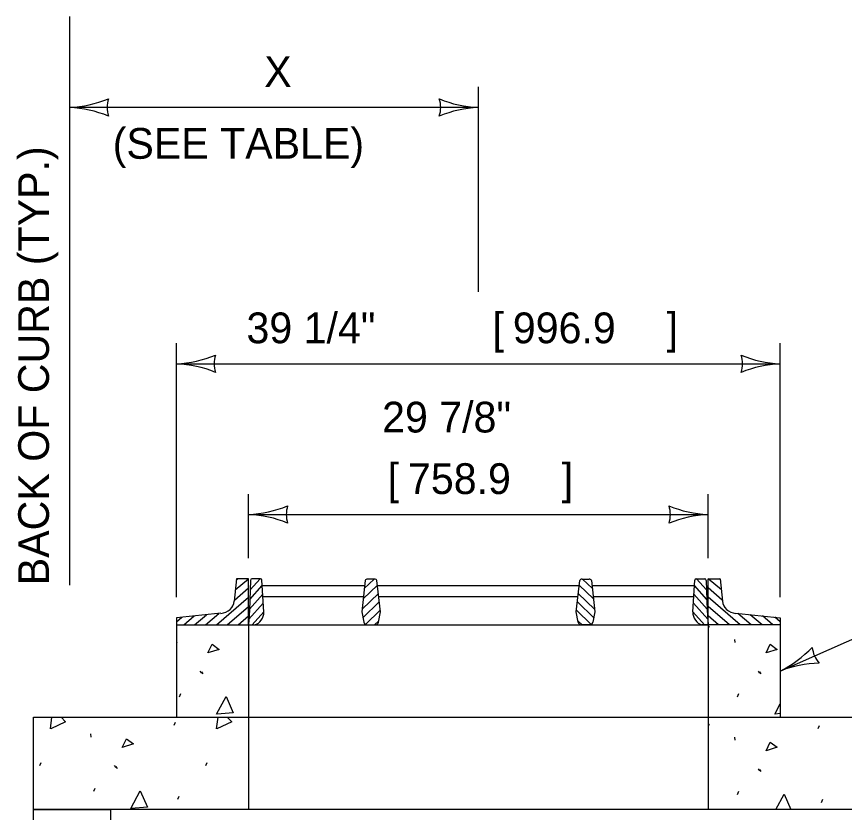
# Model space of a CAD drawing. Extents: x 49991.4 to 50041.6, y 49987.6 to 50011.4.
# Drawn here: x 50025.96 to 50027.575, y 49992.221 to 49993.773 of the extents above; entities that cross this region are included whole.
import ezdxf

# ---------------------------------------------------------------- set-up
doc = ezdxf.new("R2010")
doc.units = 0
for name, color, linetype in [('Level 1', 7, 'Continuous'), ('Level 2', 7, 'Continuous'), ('Level 3', 7, 'Continuous')]:
    doc.layers.add(name, color=color, linetype=linetype)

msp = doc.modelspace()

# ---------------------------------------------------------------- linework, layer by layer
at = {"layer": 'Level 1'}
for p, q in [((50026.3889, 49992.6769), (50026.3848, 49992.633)), ((50026.3868, 49992.655), (50026.4124, 49992.6769)), ((50026.3887, 49992.6748), (50026.3912, 49992.6769)), ((50026.4128, 49992.6769), (50026.3889, 49992.6769)), ((50026.4128, 49992.5869), (50026.4128, 49992.6769)), ((50026.4156, 49992.6553), (50026.435, 49992.6769)), ((50026.4358, 49992.6769), (50026.4192, 49992.6769)), ((50026.6385, 49992.6577), (50026.6574, 49992.676)), ((50026.6585, 49992.676), (50026.6449, 49992.676)), ((50027.0634, 49992.676), (50027.077, 49992.676)), ((50027.0834, 49992.6577), (50027.0645, 49992.676)), ((50027.2861, 49992.6769), (50027.3027, 49992.6769)), ((50027.3063, 49992.6553), (50027.2869, 49992.6769)), ((50027.3091, 49992.5869), (50027.3091, 49992.6769)), ((50027.3091, 49992.6769), (50027.3331, 49992.6769)), ((50027.3351, 49992.655), (50027.3095, 49992.6769)), ((50027.3333, 49992.6748), (50027.3307, 49992.6769)), ((50027.3331, 49992.6769), (50027.3371, 49992.633)), ((50026.385, 49992.6353), (50026.4128, 49992.6591)), ((50026.4162, 49992.6738), (50026.4142, 49992.6158)), ((50026.4149, 49992.6364), (50026.4394, 49992.6636)), ((50026.4424, 49992.6127), (50026.4388, 49992.6739)), ((50026.4394, 49992.6636), (50026.6391, 49992.6636)), ((50026.6401, 49992.6732), (50026.6336, 49992.6124)), ((50026.6363, 49992.6376), (50026.6642, 49992.6645)), ((50026.6698, 49992.6124), (50026.6632, 49992.6732)), ((50026.6643, 49992.6636), (50027.0576, 49992.6636)), ((50027.0521, 49992.6124), (50027.0587, 49992.6732)), ((50027.0856, 49992.6376), (50027.0577, 49992.6645)), ((50027.0818, 49992.6732), (50027.0883, 49992.6124)), ((50027.0828, 49992.6636), (50027.2825, 49992.6636)), ((50027.2795, 49992.6127), (50027.2832, 49992.6739)), ((50027.307, 49992.6364), (50027.2825, 49992.6636)), ((50027.3057, 49992.6738), (50027.3077, 49992.6158)), ((50027.3369, 49992.6353), (50027.3091, 49992.6591)), ((50026.4142, 49992.6175), (50026.4404, 49992.6466)), ((50026.6341, 49992.6175), (50026.6659, 49992.6482)), ((50027.0878, 49992.6175), (50027.056, 49992.6482)), ((50027.3077, 49992.6175), (50027.2815, 49992.6466)), ((50026.3498, 49992.5869), (50026.4128, 49992.6409)), ((50026.4134, 49992.5983), (50026.4414, 49992.6295)), ((50026.4407, 49992.6421), (50026.6368, 49992.6421)), ((50026.6357, 49992.601), (50026.6677, 49992.6319)), ((50026.6666, 49992.6421), (50027.0553, 49992.6421)), ((50027.0862, 49992.601), (50027.0542, 49992.6319)), ((50027.0851, 49992.6421), (50027.2812, 49992.6421)), ((50027.3085, 49992.5983), (50027.2805, 49992.6295)), ((50027.3721, 49992.5869), (50027.3091, 49992.6409)), ((50026.3711, 49992.5869), (50026.4128, 49992.6228)), ((50026.4142, 49992.6158), (50026.4128, 49992.5869)), ((50026.4195, 49992.5869), (50026.4424, 49992.6124)), ((50026.6336, 49992.6124), (50026.6373, 49992.5922)), ((50026.6408, 49992.588), (50026.6694, 49992.6156)), ((50026.6661, 49992.5922), (50026.6698, 49992.6124)), ((50027.0558, 49992.5922), (50027.0521, 49992.6124)), ((50027.0811, 49992.588), (50027.0525, 49992.6156)), ((50027.0883, 49992.6124), (50027.0846, 49992.5922)), ((50027.3024, 49992.5869), (50027.2795, 49992.6124)), ((50027.3077, 49992.6158), (50027.3091, 49992.5869)), ((50027.3509, 49992.5869), (50027.3091, 49992.6228)), ((50026.3583, 49992.6095), (50026.2722, 49992.601)), ((50026.2722, 49992.5931), (50026.2825, 49992.602)), ((50026.2722, 49992.601), (50026.2722, 49992.5869)), ((50026.2862, 49992.5869), (50026.3065, 49992.6044)), ((50026.3074, 49992.5869), (50026.3305, 49992.6067)), ((50026.3286, 49992.5869), (50026.3545, 49992.6091)), ((50026.3923, 49992.5869), (50026.4128, 49992.6046)), ((50026.6584, 49992.5869), (50026.6666, 49992.5949)), ((50027.0635, 49992.5869), (50027.0553, 49992.5949)), ((50027.3296, 49992.5869), (50027.3091, 49992.6046)), ((50027.3636, 49992.6095), (50027.4497, 49992.601)), ((50027.3933, 49992.5869), (50027.3674, 49992.6091)), ((50027.4145, 49992.5869), (50027.3914, 49992.6067)), ((50027.4357, 49992.5869), (50027.4154, 49992.6044)), ((50027.4497, 49992.5931), (50027.4394, 49992.602)), ((50027.4497, 49992.601), (50027.4497, 49992.5869)), ((50026.2722, 49992.5869), (50026.2722, 49992.4069)), ((50026.2722, 49992.5869), (50026.4128, 49992.5869)), ((50026.2722, 49992.5869), (50027.3091, 49992.5869)), ((50026.4128, 49992.5869), (50026.4244, 49992.5869)), ((50026.4128, 49992.5869), (50026.4128, 49992.2269)), ((50026.6438, 49992.5869), (50026.6596, 49992.5869)), ((50027.0782, 49992.5869), (50027.0623, 49992.5869)), ((50027.3091, 49992.5869), (50027.2975, 49992.5869)), ((50027.3091, 49992.5869), (50027.3091, 49992.2269)), ((50027.4497, 49992.5869), (50027.3091, 49992.5869)), ((50027.4497, 49992.5869), (50027.4497, 49992.4069)), ((50026.2722, 49992.5543), (50026.2724, 49992.5524)), ((50027.3606, 49992.5585), (50027.3613, 49992.5524)), ((50026.3179, 49992.497), (50026.3206, 49992.493)), ((50026.3206, 49992.4955), (50026.3233, 49992.4914)), ((50027.4068, 49992.497), (50027.4095, 49992.493)), ((50027.4095, 49992.4955), (50027.4122, 49992.4914)), ((50026.278, 49992.4469), (50026.2807, 49992.453)), ((50027.3668, 49992.4469), (50027.3695, 49992.453)), ((50026.2677, 49992.3912), (50026.2704, 49992.3973)), ((50027.5238, 49992.3849), (50027.5265, 49992.391)), ((50026.1045, 49992.3742), (50026.1052, 49992.3681)), ((50027.3606, 49992.3679), (50027.3613, 49992.3619)), ((50026.0052, 49992.3127), (50026.0079, 49992.3188)), ((50026.1507, 49992.3127), (50026.1534, 49992.3086)), ((50026.1534, 49992.3112), (50026.1561, 49992.3071)), ((50026.3293, 49992.3127), (50026.332, 49992.3188)), ((50027.4068, 49992.3064), (50027.4095, 49992.3024)), ((50027.4095, 49992.3049), (50027.4122, 49992.3008)), ((50026.1107, 49992.2625), (50026.1134, 49992.2686)), ((50027.3668, 49992.2563), (50027.3695, 49992.2624)), ((50026.2745, 49992.247), (50026.2772, 49992.2531)), ((50027.5306, 49992.2407), (50027.5333, 49992.2468)), ((50025.9932, 49991.3269), (50025.9932, 49992.2269))]:
    msp.add_line(p, q, dxfattribs=at)
for points in [[(50027.3091, 49992.5848), (50027.3116, 49992.5822), (50027.3091, 49992.581)], [(50026.3335, 49992.5322), (50026.3416, 49992.5491), (50026.3551, 49992.539), (50026.3335, 49992.5322)], [(50027.4223, 49992.5322), (50027.4305, 49992.5491), (50027.444, 49992.539), (50027.4223, 49992.5322)], [(50026.3504, 49992.413), (50026.3687, 49992.4475), (50026.3829, 49992.4157), (50026.3511, 49992.413)], [(50027.4393, 49992.413), (50027.4497, 49992.4328)], [(50026.0259, 49992.3842), (50026.0291, 49992.4069)], [(50026.0467, 49992.4069), (50026.0555, 49992.3978), (50026.0266, 49992.3844)], [(50026.3501, 49992.3842), (50026.3532, 49992.4069)], [(50026.3708, 49992.4069), (50026.3797, 49992.3978), (50026.3507, 49992.3844)], [(50027.4497, 49992.4139), (50027.4399, 49992.413)], [(50027.3091, 49992.3942), (50027.3116, 49992.3916), (50027.3091, 49992.3904)], [(50026.1662, 49992.3479), (50026.1744, 49992.3648), (50026.1879, 49992.3547), (50026.1662, 49992.3479)], [(50027.4223, 49992.3416), (50027.4305, 49992.3585), (50027.444, 49992.3484), (50027.4223, 49992.3416)], [(50026.1832, 49992.2287), (50026.2014, 49992.2632), (50026.2156, 49992.2314), (50026.1838, 49992.2287)], [(50027.4416, 49992.2269), (50027.4575, 49992.257), (50027.4709, 49992.2269)], [(50025.9932, 49992.2269), (50026.1432, 49992.2269), (50026.1432, 49991.3269)]]:
    msp.add_lwpolyline(points, dxfattribs=at)
msp.add_lwpolyline([(50025.9932, 49992.2269), (50025.9932, 49992.4069), (50027.7287, 49992.4069), (50027.7287, 49992.2269)], close=True, dxfattribs=at)
for centre, major_axis, ratio, start_param, end_param in [((50026.4192, 49992.6736), (0, 0.00334), 0.898406, 0, 1.518438), ((50026.4358, 49992.6736), (0, 0.00334), 0.898406, 4.799667, 6.283204), ((50026.6441, 49992.6721), (0.00417, 0), 0.966535, 1.388426, 2.855422), ((50026.6592, 49992.6721), (-0.00418, 0), 0.966535, 3.427776, 4.894775), ((50027.0627, 49992.6721), (0.00418, 0), 0.966535, 1.38841, 2.855409), ((50027.0778, 49992.6721), (-0.00417, 0), 0.966535, 3.427763, 4.894759), ((50027.2861, 49992.6736), (0, 0.00334), 0.898406, 6.283167, 7.766704), ((50027.3027, 49992.6736), (0, 0.00334), 0.898406, 4.764748, 6.283185), ((50026.3549, 49992.635), (0.03, 0), 0.857143, 4.827266, 6.204597), ((50027.367, 49992.635), (-0.03, 0), 0.857143, 0.078588, 1.45592), ((50026.4193, 49992.612), (0, 0.0257), 0.898406, 3.361832, 4.736544), ((50027.3026, 49992.612), (0, 0.0257), 0.898406, 1.546641, 2.921353), ((50026.6438, 49992.5933), (-0.00658, 0), 0.966535, 0.174538, 1.570796), ((50026.6596, 49992.5933), (-0.00658, 0), 0.966535, 1.570796, 2.967065), ((50027.0623, 49992.5933), (-0.00658, 0), 0.966535, 0.174528, 1.570796), ((50027.0782, 49992.5933), (-0.00658, 0), 0.966535, 1.570796, 2.967054)]:
    msp.add_ellipse(centre, major_axis=major_axis, ratio=ratio, start_param=start_param, end_param=end_param, dxfattribs=at)
at = {"layer": 'Level 3'}
for p, q in [((50026.0632, 49993.7732), (50026.0632, 49992.6642)), ((50026.861, 49993.2361), (50026.861, 49993.6359)), ((50026.861, 49993.5959), (50026.0632, 49993.5959)), ((50026.2722, 49992.641), (50026.2722, 49993.1361)), ((50027.4497, 49992.641), (50027.4497, 49993.1361)), ((50026.2722, 49993.0961), (50027.4497, 49993.0961)), ((50026.4128, 49992.7169), (50026.4128, 49992.8421)), ((50027.3091, 49992.7169), (50027.3091, 49992.8421)), ((50026.4128, 49992.8021), (50027.3091, 49992.8021)), ((50027.4497, 49992.4969), (50027.7078, 49992.6112))]:
    msp.add_line(p, q, dxfattribs=at)
for centre, radius, start, end in [((50026.0517, 49993.8286), 0.233, 272.8273, 292.0772), ((50026.1914, 49993.5959), 0.0548, 162.1388, 197.8612), ((50026.8701, 49993.818), 0.2223, 247.456, 267.6395), ((50026.7327, 49993.5959), 0.0548, 342.1388, 17.8612), ((50026.8701, 49993.818), 0.2223, 247.456, 267.6395), ((50026.7327, 49993.5959), 0.0548, 342.1388, 17.8612), ((50026.054, 49993.3737), 0.2223, 67.456, 87.6395), ((50026.8724, 49993.3632), 0.233, 92.8273, 112.0772), ((50026.8724, 49993.3632), 0.233, 92.8273, 112.0772), ((50026.2607, 49993.3288), 0.233, 272.8273, 292.0772), ((50026.2607, 49993.3288), 0.233, 272.8273, 292.0772), ((50026.4004, 49993.0961), 0.0548, 162.1388, 197.8612), ((50026.4004, 49993.0961), 0.0548, 162.1388, 197.8612), ((50027.4589, 49993.3182), 0.2223, 247.456, 267.6395), ((50027.3215, 49993.0961), 0.0548, 342.1388, 17.8612), ((50027.4589, 49993.3182), 0.2223, 247.456, 267.6395), ((50027.3215, 49993.0961), 0.0548, 342.1388, 17.8612), ((50026.263, 49992.8739), 0.2223, 67.456, 87.6395), ((50026.263, 49992.8739), 0.2223, 67.456, 87.6395), ((50027.4612, 49992.8634), 0.233, 92.8273, 112.0772), ((50027.4612, 49992.8634), 0.233, 92.8273, 112.0772), ((50026.4013, 49993.0349), 0.233, 272.8273, 292.0772), ((50026.4013, 49993.0349), 0.233, 272.8273, 292.0772), ((50026.541, 49992.8021), 0.0548, 162.1388, 197.8612), ((50026.541, 49992.8021), 0.0548, 162.1388, 197.8612), ((50027.3182, 49993.0243), 0.2223, 247.456, 267.6395), ((50027.1809, 49992.8021), 0.0548, 342.1388, 17.8612), ((50027.3182, 49993.0243), 0.2223, 247.456, 267.6395), ((50027.1809, 49992.8021), 0.0548, 342.1388, 17.8612), ((50026.4037, 49992.58), 0.2223, 67.456, 87.6395), ((50026.4037, 49992.58), 0.2223, 67.456, 87.6395), ((50027.3206, 49992.5694), 0.233, 92.8273, 112.0772), ((50027.3206, 49992.5694), 0.233, 92.8273, 112.0772), ((50027.345, 49992.7051), 0.233, 296.7082, 315.9581), ((50027.5669, 49992.5489), 0.0548, 186.0197, 221.7421), ((50027.5313, 49992.2901), 0.2223, 91.3369, 111.5204)]:
    msp.add_arc(centre, radius, start, end, dxfattribs=at)

# ---------------------------------------------------------------- texts
at = {"layer": 'Level 2'}
for s, rotation, p in [('X', 360, (50026.4432, 49993.6359)), ('(SEE TABLE)', 360, (50026.1476, 49993.4959)), ('BACK OF CURB (TYP.)', 90, (50026.0232, 49992.6642)), ('39 1/4" ', 360, (50026.4086, 49993.1361)), ('[', 360, (50026.8886, 49993.1361)), ('996.9', 360, (50026.9283, 49993.1361)), (']', 360, (50027.2283, 49993.1361)), ('29 7/8"', 360, (50026.6732, 49992.9621)), ('[', 360, (50026.684, 49992.8421)), ('758.9', 360, (50026.7237, 49992.8421)), (']', 360, (50027.0237, 49992.8421))]:
    msp.add_text(s, height=0.06, rotation=rotation, dxfattribs=at).set_placement(p)

doc.saveas('drawing.dxf')
